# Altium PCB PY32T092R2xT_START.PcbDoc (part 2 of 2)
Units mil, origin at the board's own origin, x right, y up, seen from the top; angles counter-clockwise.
Board outline 1771.65 x 3866.06 mil, 2 copper layers (Top Layer, Bottom Layer), stack 21 mil thick; 144 components, 162 nets, 571 pads, 266 vias.
Unrouted connection lines stored in the file: 5.
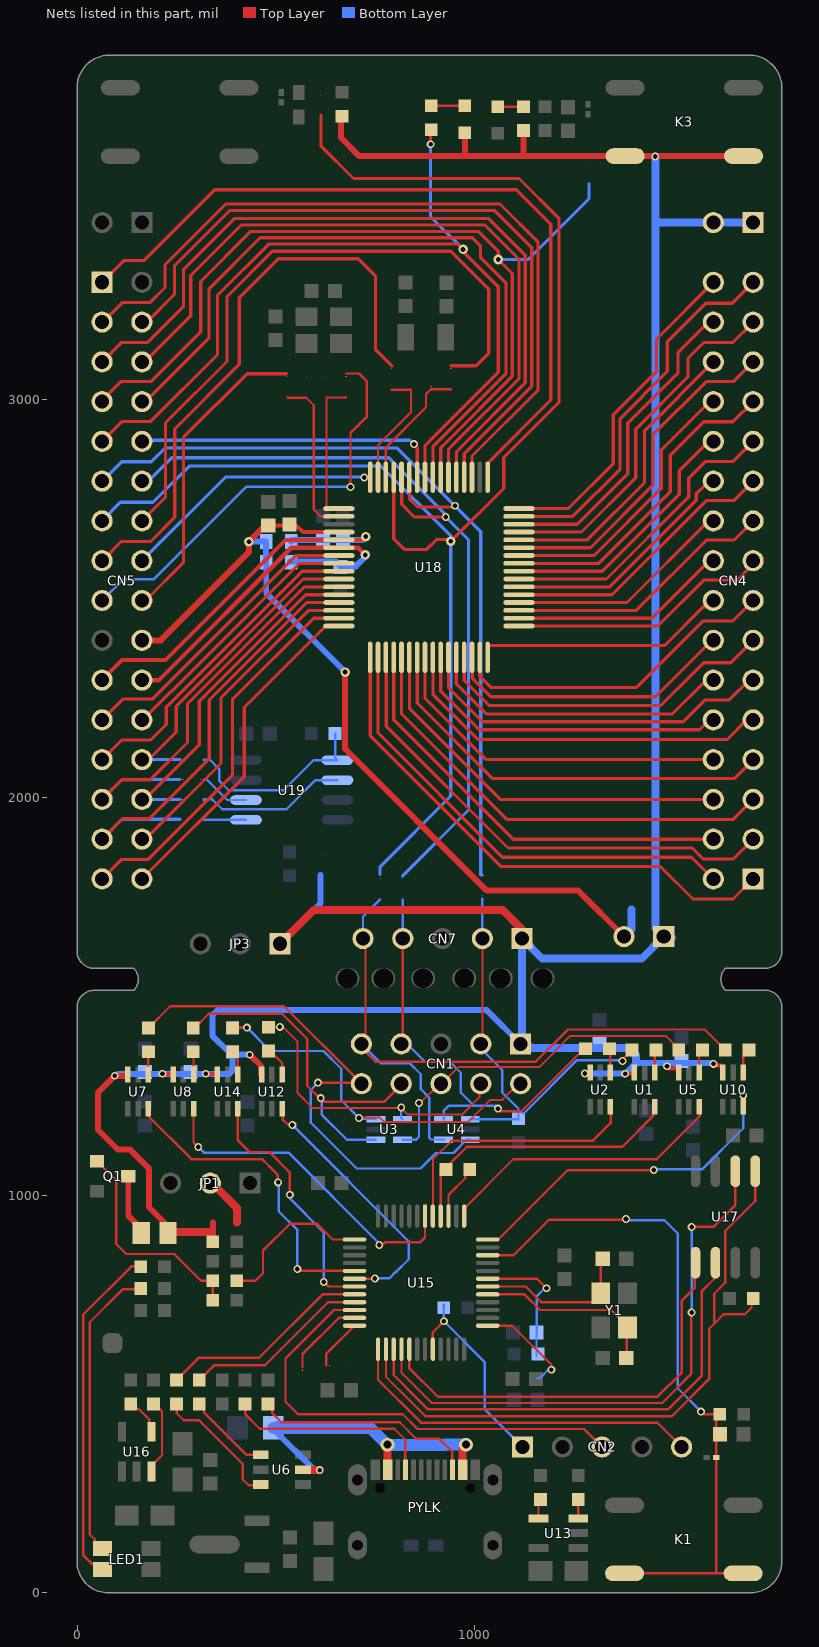
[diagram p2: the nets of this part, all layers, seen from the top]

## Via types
v1: diameter 19.68, hole 11.81, Top Layer to Bottom Layer, tented both sides, 132 vias
v2: diameter 19.68, hole 11.81, Top Layer to Bottom Layer, 72 vias
v3: diameter 24, hole 12, Top Layer to Bottom Layer, tented both sides, 50 vias
v4: diameter 35, hole 20, Top Layer to Bottom Layer, tented both sides, 8 vias
v5: diameter 30, hole 15, Top Layer to Bottom Layer, tented both sides, 2 vias
v6: diameter 40, hole 20, Top Layer to Bottom Layer, tented both sides, 2 vias

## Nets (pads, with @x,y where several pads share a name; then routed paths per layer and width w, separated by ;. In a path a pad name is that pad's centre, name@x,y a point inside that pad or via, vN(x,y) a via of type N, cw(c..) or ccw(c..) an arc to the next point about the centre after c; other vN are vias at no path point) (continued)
NetLED1_3: LED1.3 R6.1 | length 884.3
  Top Layer w6: LED1.3@44.29,58.63 LED1.3@59,43.93 ; LED1.3@64,58.93 49.29,73.63 36.1,73.63 16.02,93.72 16.02,700.45 136.61,821.05 159.08,821.05 R6.1@160.02,820.12
NetLED1_4: LED1.4 R4.1 | length 755.1
  Top Layer w6: LED1.4@56.68,98.62 44.37,110.92 44.37,134.85 32.02,147.21 32.02,680.45 115.41,763.84 158.74,763.84 R4.1@160.02,765.12
NetLED_PA2_2: LED_PA2.2 R53.1 | length 85
  Top Layer w6: R53.1@890.21,3738.35 LED_PA2.2@975.21,3738.35
NetLED_VDD*_1: LED_VDD*.1 R38.1 | length 65
  Top Layer w6: LED_VDD*.1@1057.21,3736.35 R38.1@1122.21,3736.35
NetPYLK_A5: PYLK.A5 R1.2 | length 530.3
  Top Layer w6: R1.2@422.51,475.11 422.51,449.93 459.53,412.91 797.6,412.91 825.35,385.15 825.35,310.66 PYLK.A5@826.01,310.01
NetPYLK_B5: PYLK.B5 R3.1 | length 566
  Top Layer w6: R3.1@480.02,475.12 490.33,464.81 490.33,452.45 513.87,428.91 811.12,428.91 852.68,387.36 911.56,387.36 943.19,355.73 943.19,310.94 PYLK.B5@944.12,310.01
NetQ1_1: Q1.1 R19.1 R20.2 | length 559
  Top Layer w6: Q1.1@50.02,1084.92 51.98,1084.92 63.73,1073.17 63.73,1071.35 98.48,1036.6 98.48,877.45 123.87,852.06 244.46,852.06 311.62,784.9 R19.1@341.54,784.9 ; R20.2@341.53,736 R19.1@341.53,784.89
NetQ1_3: Q1.3 R15.1 | length 166.5
  Top Layer w6: Q1.3@125.51,1044.27 Q1.3@128.76,1047.52 ; R15.1@161.55,905.12 R15.1@161.55,911.02
  Top Layer w15: Q1.3@128.76,1047.52 128.76,948.4 161.55,915.6 R15.1@161.55,905.12
NetR2_1: R2.1 U1.4 | length 57.9
  Top Layer w6: U1.4@1452.24,1308.42 1452.24,1362.13 R2.1@1455.22,1365.12
NetR7_1: R7.1 U2.4 | length 57.8
  Top Layer w6: R7.1@1338.08,1365.12 1340.81,1362.38 U2.4@1340.81,1308.42
NetR10_1: R10.1 U5.4 | length 60.3
  Top Layer w6: U5.4@1563.67,1308.42 1563.67,1356.42 R10.1@1572.37,1365.12
NetR11_1: R11.1 U6.3 | length 332.9
  Top Layer w6: R11.1@250.02,475.12 250.79,474.34 250.79,451.8 268.43,434.16 306.81,434.16 416.26,324.72 416.26,285.99 431.64,270.6 459.75,270.6 U6.3@461.55,272.4
NetR12_1: R12.1 U6.1 | length 227.7
  Top Layer w6: R12.1@308.77,480.12 319.16,469.72 319.16,453.79 426.01,346.94 U6.1@471.99,346.94
NetR13_1: R13.1 U7.4 | length 59
  Top Layer w6: R13.1@173.56,1360.12 179.15,1354.52 U7.4@179.15,1303.42
NetR14_1: R14.1 U8.4 | length 60.8
  Top Layer w6: R14.1@280.96,1360.13 R14.1@290.84,1350.25 ; U8.4@292.87,1303.42 R14.1@292.87,1350.24
NetR18_1: R18.1 U10.4 | length 62.7
  Top Layer w6: U10.4@1675.1,1308.42 1675.1,1350.71 R18.1@1689.51,1365.12
NetR22_1: R22.1 U12.4 | length 75.3
  Top Layer w6: R22.1@481.65,1362.23 485.64,1362.23 515.73,1332.14 U12.4@515.73,1303.42
NetR24_2: R24.2 U13.4 | length 49.6
  Top Layer w6: U13.4@1160.02,187.62 1160.02,230.12 R24.2@1165.02,235.12
NetR25_2: R25.2 U13.3 | length 47.5
  Top Layer w6: U13.3@1260.02,187.62 R25.2@1260.02,235.12
NetR26_1: R26.1 U14.4 | length 62.8
  Top Layer w6: R26.1@391.22,1360.82 404.3,1347.73 U14.4@404.3,1303.42
NetR27_2: R27.2 U15.1 | length 256.3
  Top Layer w6: U15.1@1032.34,671.85 1094.2,671.85 1192.47,573.57 v2(1192.47,561)
  Bottom Layer w6: 1158.36,539.95 1163.62,539.95 1184.67,561 v2(1192.47,561)
NetR29_2: R29.2 U16.4 | length 96.1
  Top Layer w6: R29.2@135.02,475.12 147.02,463.12 154.46,463.12 181.52,436.06 181.52,411.12 U16.4@187.52,405.12
NetR30_2: R30.2 U16.3 | length 188.5
  Top Layer w6: U16.3@187.52,305.12 187.52,320.12 213.57,346.17 213.57,455.79 207.02,462.35 207.02,463.12 R30.2@195.02,475.12
NetR31_1: R31.1 U15.36 | length 129.6
  Top Layer w6: 626.23,571.86 626.23,600.38 U15.36@697.7,671.85
NetR33_1: R33.1 U15.35 | length 201.4
  Top Layer w6: 566.98,567.51 566.98,600.5 658.02,691.54 U15.35@697.7,691.54
NetR44_1: R44.1 R46.1 U19.1 | length 486
  Bottom Layer w6: 318.06,2094.88 333.56,2094.88 357.32,2071.12 357.32,2042.15 381.47,2018.01 519.43,2018.01 594.74,2093.32 U19.1@654.57,2093.32 648.75,2099.14 R44.1@648.75,2160.34
NetR47_1: R47.1 U19.2 | length 376.2
  Bottom Layer w6: 318.06,1994.88 319.93,1993.01 ; 321.81,1994.88 340.06,1994.88 365.01,1969.93 526.44,1969.93 599.82,2043.32 U19.2@654.57,2043.32
NetR48_2: R48.2 U19.6 | length 127.9
  Bottom Layer w6: 318.06,2044.88 326.03,2044.88 377.6,1993.32 U19.6@424.57,1993.32
NetR49_2: R49.2 U19.5 | length 107.2
  Bottom Layer w6: 318.06,1944.88 319.62,1943.32 U19.5@424.57,1943.32
OSC_32INa: R42.1 R59.2 U18.46 | length 318.7
  Top Layer w6: U18.46@776.4,2804.8 776.4,2860.09 776.4,2879.71 877.4,2980.71 877.4,3013.66 889.68,3025.94 939.19,3025.94 940.02,3025.12
OSC_32OUTa: R41.1 R61.2 U18.47 | length 303.4
  Top Layer w6: U18.47@756.72,2804.8 756.72,2885.01 839.69,2967.98 839.69,3025.12 791.02,3025.12
OSC_INa: R40.1 R55.2 U18.49 | length 358
  Top Layer w6: U18.49@658.3,2726.07 629.9,2726.07 627.22,2728.75 627.22,2860.5 627.28,2860.57 627.28,3005.31 675.57,3005.31 675.97,3005.72 676.23,3005.46
OSC_OUTa: R39.1 R57.2 U18.50 | length 406.5
  Top Layer w6: 529.27,3005.72 530.5,3004.49 576.23,3004.49 595.02,2985.7 595.02,2723.69 611.59,2707.11 657.57,2707.11 U18.50@658.3,2706.38
PA0: CN5.7 R58.2 U18.39 | length 2256.3
  Top Layer w8: CN5.7@63.06,2994.88 63.06,2998.16 110.02,3045.12 185.47,3045.12 311.06,3170.71 311.06,3296.88 437.06,3422.88 1009.06,3422.88 1058.95,3372.99 v3(1058.95,3352.13) 1094.06,3317.01 1094.06,3058.47 930.29,2894.7 930.29,2894.61 914.2,2878.53 U18.39@914.2,2804.8
  Bottom Layer w8: v3(1058.95,3352.13) 1134.03,3352.13 1287.02,3505.12 1287.02,3543.12
PA1: CN5.8 U18.40 | length 1786.7
  Top Layer w8: CN5.8@163.06,2994.88 171.24,2994.88 332.06,3155.7 332.06,3278.88 460.06,3406.88 994.06,3406.88 1014.1,3386.84 1014.1,3357.84 1078.06,3293.88 1078.06,3065.1 914.29,2901.33 914.29,2901.24 894.51,2881.46 U18.40@894.51,2804.8
PA2: CN5.9 R53.2 U18.41 | length 2234.7
  Top Layer w8: CN5.9@63.06,2894.88 113.29,2945.12 185.18,2945.12 353.06,3112.99 353.06,3261.88 482.06,3390.88 957.2,3390.88 v3(970.59,3377.49) 970.59,3371.99 1059.06,3283.52 1059.06,3068.73 898.29,2907.96 898.29,2907.87 874.83,2884.41 U18.41@874.83,2804.8 ; v1(888.98,3641.73) 888.98,3677.11 R53.2@895.98,3684.12
  Bottom Layer w8: v1(888.98,3641.73) 888.98,3459.1 v3(970.59,3377.49)
PA3: CN5.10 U18.42 | length 775.8
  Top Layer w8: v1(847.05,2887.91) 855.14,2879.82 U18.42@855.14,2804.8
  Bottom Layer w8: CN5.10@163.06,2894.88 166.06,2897.88 837.08,2897.88 v1(847.05,2887.91)
PA4: CN5.11 R51.2 U18.43 | length 2118.7
  Top Layer w8: U18.43@835.46,2804.8 835.46,2750.48 856.06,2729.88 947.06,2729.88 v1(950.06,2732.88)
  Bottom Layer w8: CN5.11@63.06,2794.88 112.06,2843.88 187.06,2843.88 221.06,2877.88 805.06,2877.88 v1(950.06,2732.88) 1014.94,2668 1014.94,1805.18 1018.95,1805.18
PA5: CN5.12 R52.2 U18.44 | length 2039.7
  Top Layer w8: U18.44@815.77,2804.8 816.5,2804.07 816.5,2736.44 848.06,2704.88 v1(927.06,2704.88)
  Bottom Layer w8: CN5.12@163.06,2794.88 179.06,2794.88 238.06,2853.88 784.06,2853.88 927.06,2710.88 v1(927.06,2704.88) 984.06,2647.88 984.06,1968.22 818.95,1803.12
PA6: CN5.14 R42.2 | length 1665.8
  Top Layer w8: CN5.14@163.06,2694.88 222.48,2754.31 222.48,2941.25 377.06,3095.83 377.06,3258.88 491.06,3372.88 939.06,3372.88 1035.06,3276.88 1035.06,3116.88 1003.29,3085.12 940.02,3085.12
PA7: CN5.15 R41.2 | length 1490.2
  Top Layer w8: CN5.15@63.06,2594.88 111.29,2643.12 184.95,2643.12 245.61,2703.77 245.61,2926.13 408.06,3088.58 408.06,3255.88 506.06,3353.88 707.06,3353.88 750.06,3310.88 750.06,3126.07 791.02,3085.12
PA8: CN5.16 U18.48 | length 661.6
  Top Layer w8: v1(722.07,2804.24) 722.63,2804.8 U18.48@737.03,2804.8
  Bottom Layer w8: CN5.16@163.06,2594.88 373.29,2805.12 721.19,2805.12 v1(722.07,2804.24)
PA9: CN5.17 R40.2 | length 1085.4
  Top Layer w6: 676.05,3065.63 676.23,3065.63 ; 676.23,3065.46 709.23,3065.46 727.92,3046.76 727.92,2956.34 687.5,2915.91 v1(687.5,2780.37)
  Bottom Layer w6: CN5.17@63.06,2494.88 116.06,2547.88 192.62,2547.88 425.11,2780.37 v1(687.5,2780.37)
PA10: CN5.18 R39.2 | length 784.4
  Top Layer w8: CN5.18@163.06,2494.88 172.06,2494.88 267.39,2590.21 267.39,2904.82 427.69,3065.12 527.02,3065.12
PA13: CN5.23 U18.55 | length 766.3
  Top Layer w8: CN5.23@63.06,2194.88 115.29,2247.12 189.52,2247.12 282.02,2339.61 549.64,2607.23 657.57,2607.23 U18.55@658.3,2607.96
PA14: CN5.24 U18.56 | length 659.3
  Top Layer w8: CN5.24@163.06,2194.88 164.44,2193.5 311.02,2340.08 559.2,2588.27 U18.56@658.3,2588.27
PA15: CN5.25 U18.57 | length 817
  Top Layer w8: CN5.25@63.06,2094.88 112.29,2144.12 185.04,2144.12 224.14,2183.21 224.14,2226.74 565.98,2568.59 U18.57@658.3,2568.59
PB0: CN5.26 R46.2 U18.58 | length 816.3
  Top Layer w8: CN5.26@163.06,2094.88 179.83,2094.88 249.26,2164.31 249.26,2229.24 568.92,2548.9 U18.58@658.3,2548.9
  Bottom Layer w8: CN5.26@163.06,2094.88 258.06,2094.88
PB1: CN5.27 R48.1 U18.59 | length 1089.1
  Top Layer w8: CN5.27@63.06,1994.88 112.29,2044.12 183.82,2044.12 277.66,2137.95 277.66,2235.01 571.86,2529.22 U18.59@658.3,2529.22
  Bottom Layer w8: CN5.27@63.06,1994.88 113.06,2044.88 258.06,2044.88
PB2: CN5.28 R47.2 U18.60 | length 867.7
  Top Layer w8: CN5.28@163.06,1994.88 169.96,1994.88 307.36,2132.28 307.36,2242.09 574.57,2509.29 658.06,2509.29 U18.60@658.3,2509.53
  Bottom Layer w8: CN5.28@163.06,1994.88 258.06,1994.88
PB3: CN5.29 R49.1 U18.61 | length 1143.9
  Top Layer w8: CN5.29@63.06,1894.88 114.29,1946.12 181.72,1946.12 332.56,2096.95 332.56,2244.66 577.75,2489.85 U18.61@658.3,2489.85
  Bottom Layer w8: CN5.29@63.06,1894.88 113.06,1944.88 258.06,1944.88
PB4: CN5.30 U18.62 | length 830.1
  Top Layer w8: CN5.30@163.06,1894.88 171.62,1894.88 361.96,2085.22 361.96,2250.06 582.06,2470.16 U18.62@658.3,2470.16
PB5: CN5.31 U18.63 | length 978.2
  Top Layer w8: CN5.31@63.06,1794.88 112.29,1844.12 178.76,1844.12 390.56,2055.91 390.56,2246.08 594.95,2450.48 U18.63@658.3,2450.48
PB6: CN5.32 U18.64 | length 860.5
  Top Layer w8: CN5.32@163.06,1794.88 420.26,2052.08 420.26,2225.9 625.15,2430.79 U18.64@658.3,2430.79
PB7: CN4.1 U18.1 | length 1350.5
  Top Layer w8: U18.1@737.03,2352.06 737.03,2155.29 1066.33,1825.98 1466.82,1825.98 1548.43,1744.38 1649.11,1744.38 CN4.1@1699.61,1794.88
PB8: CN4.2 U18.2 | length 1184.9
  Top Layer w8: U18.2@756.72,2352.06 756.72,2162.14 1069.25,1849.61 1544.88,1849.61 CN4.2@1599.61,1794.88
PB9: CN4.3 U18.3 | length 1254.7
  Top Layer w8: U18.3@776.4,2352.06 777.51,2350.95 777.51,2178.77 1083.45,1872.83 1546.69,1872.83 1574.41,1845.12 1649.84,1845.12 CN4.3@1699.61,1894.88
PB10: CN4.4 U18.4 | length 1084.9
  Top Layer w8: U18.4@796.09,2352.06 796.09,2195.01 1096.21,1894.88 CN4.4@1599.61,1894.88
PB11: CN4.5 U18.5 | length 1157
  Top Layer w8: U18.5@815.77,2352.06 815.77,2210.18 1081.83,1944.12 1648.84,1944.12 CN4.5@1699.61,1994.88
PB12: CN4.6 U18.6 | length 987.2
  Top Layer w8: U18.6@835.46,2352.06 835.46,2223.78 1064.35,1994.88 CN4.6@1599.61,1994.88
PB13: CN4.7 U18.7 | length 1057.9
  Top Layer w8: U18.7@855.14,2352.06 855.14,2237.12 1045.15,2047.12 1651.84,2047.12 CN4.7@1699.61,2094.88
PB14: CN4.8 U18.8 | length 891.6
  Top Layer w8: U18.8@874.83,2352.06 874.83,2249.17 1029.12,2094.88 CN4.8@1599.61,2094.88
PB15: CN4.9 U18.9 | length 965.9
  Top Layer w8: U18.9@894.51,2352.06 894.51,2259.02 1008.41,2145.12 1257.29,2145.12 1633.94,2145.12 1683.71,2194.88 CN4.9@1699.61,2194.88
PC0: CN4.10 U18.10 | length 820.8
  Top Layer w8: U18.10@914.2,2352.06 914.2,2267.18 1011.36,2170.02 1242.06,2170.02 1564.92,2170.02 1589.78,2194.88 CN4.10@1599.61,2194.88
PC1: CN4.11 U18.11 | length 921.3
  Top Layer w8: U18.11@933.88,2352.06 933.88,2275.35 1019.34,2189.88 1524.06,2189.88 1579.29,2245.12 1639.66,2245.12 1689.43,2294.88 CN4.11@1699.61,2294.88
PC2: CN4.12 U18.12 | length 779.2
  Top Layer w8: U18.12@953.57,2352.06 953.57,2285.32 1029.01,2209.88 1497.06,2209.88 1582.06,2294.88 CN4.12@1599.61,2294.88
PC3: CN4.13 U18.13 | length 878.6
  Top Layer w8: U18.13@973.25,2352.06 973.25,2293.75 1036.11,2230.88 1467.87,2230.88 1550.11,2313.12 1575.37,2338.38 1643.1,2338.38 CN4.13@1699.61,2394.88
PC4: CN4.14 U18.14 | length 736.9
  Top Layer w8: U18.14@992.94,2352.06 993.67,2351.33 993.67,2299.62 1040.41,2252.88 1454.26,2252.88 1596.26,2394.88 CN4.14@1599.61,2394.88
PC5: CN4.15 U18.15 | length 837.2
  Top Layer w8: U18.15@1012.62,2352.06 1012.62,2304.38 1041.11,2275.88 1405.4,2275.88 1489.63,2360.12 1572.63,2443.12 1647.84,2443.12 CN4.15@1699.61,2494.88
PC6: CN4.16 U18.16 | length 641.7
  Top Layer w8: U18.16@1032.31,2352.06 1032.31,2378.13 1036.06,2381.88 1477.06,2381.88 1574.41,2479.23 1583.96,2479.23 CN4.16@1599.61,2494.88
PC7: CN4.17 U18.17 | length 661.3
  Top Layer w8: U18.17@1111.04,2430.79 1459.97,2430.79 1575.29,2546.12 1659.02,2546.12 1699.61,2586.71 CN4.17@1699.61,2594.88
PC8: CN4.18 U18.18 | length 548.4
  Top Layer w8: U18.18@1111.04,2450.48 1444.66,2450.48 1589.06,2594.88 CN4.18@1599.61,2594.88
PC9: CN4.19 U18.19 | length 681.7
  Top Layer w8: U18.19@1111.04,2470.16 1405.93,2470.16 1582.89,2647.12 1651.84,2647.12 CN4.19@1699.61,2694.88
PC10: CN4.20 U18.20 | length 573.5
  Top Layer w8: U18.20@1111.04,2489.85 1382.62,2489.85 1586.98,2694.21 1598.93,2694.21 CN4.20@1599.61,2694.88
PC11: CN4.21 U18.21 | length 706.8
  Top Layer w8: U18.21@1111.04,2509.53 1344.9,2509.53 1581.48,2746.12 1650.84,2746.12 CN4.21@1699.61,2794.88
PC12: CN4.22 U18.22 | length 608.2
  Top Layer w8: U18.22@1111.04,2529.22 1339.4,2529.22 1556.86,2746.68 1556.86,2763.08 1583.99,2790.21 1594.93,2790.21 CN4.22@1599.61,2794.88
PC13: CN4.23 U18.23 | length 759.3
  Top Layer w8: U18.23@1111.04,2548.9 1331.08,2548.9 1537.76,2755.58 1537.76,2802.44 1579.43,2844.12 1648.84,2844.12 CN4.23@1699.61,2894.88
PC14: CN4.24 U18.24 | length 658.5
  Top Layer w8: U18.24@1111.04,2568.59 1320.77,2568.59 1514.16,2761.98 1514.16,2821.32 1587.72,2894.88 CN4.24@1599.61,2894.88
PC15: CN4.25 U18.25 | length 810.6
  Top Layer w8: U18.25@1111.04,2588.27 1311.45,2588.27 1491.46,2768.28 1491.46,2859.87 1575.71,2944.12 1648.84,2944.12 CN4.25@1699.61,2994.88
PD0: CN4.26 U18.26 | length 705.4
  Top Layer w8: U18.26@1111.04,2607.96 1300.14,2607.96 1468.79,2776.61 1468.79,2873.15 1588.84,2993.21 1597.93,2993.21 CN4.26@1599.61,2994.88
PD1: CN4.27 U18.27 | length 856.4
  Top Layer w8: U18.27@1111.04,2627.64 1290.82,2627.64 1447.62,2784.44 1447.62,2911.32 1581.41,3045.12 1649.84,3045.12 CN4.27@1699.61,3094.88
PD2: CN4.28 U18.28 | length 750.4
  Top Layer w8: U18.28@1111.04,2647.33 1282.51,2647.33 1426.83,2791.66 1426.83,2922.11 CN4.28@1599.61,3094.88
PD3: CN4.29 U18.29 | length 906.4
  Top Layer w8: U18.29@1111.04,2667.01 1268.19,2667.01 1404.46,2803.29 1404.46,2925.56 1536.02,3057.12 1536.02,3104.12 1575.02,3143.12 1647.84,3143.12 CN4.29@1699.61,3194.88
PD4: CN4.30 U18.30 | length 804.1
  Top Layer w8: U18.30@1111.04,2686.7 1257.88,2686.7 1384.31,2813.13 1384.31,2940.41 1511.02,3067.12 1511.02,3119.12 1586.78,3194.88 CN4.30@1599.61,3194.88
PD5: CN4.31 U18.31 | length 950.2
  Top Layer w8: U18.31@1111.04,2706.38 1246.56,2706.38 1365.33,2825.16 1365.33,2952.06 1484.02,3070.74 1484.02,3145.12 1581.02,3242.12 1646.84,3242.12 CN4.31@1699.61,3294.88
PD6: CN4.32 U18.32 | length 843.9
  Top Layer w8: U18.32@1111.04,2726.07 1235.25,2726.07 1347.99,2838.82 1347.99,2962.09 1457.02,3071.12 1457.02,3152.29 CN4.32@1599.61,3294.88
PD7: CN5.1 U18.33 | length 1962.1
  Top Layer w8: CN5.1@63.06,3294.88 117.56,3349.38 167.56,3349.38 345.8,3527.62 1104.32,3527.62 1191.02,3440.92 1191.02,2998.84 1032.31,2840.13 U18.33@1032.31,2804.8
PD9: CN5.3 U18.35 | length 1951.9
  Top Layer w8: CN5.3@63.06,3194.88 64.39,3194.88 113.33,3243.83 183,3243.83 221.06,3281.88 221.06,3338.96 373.72,3491.62 1063.32,3491.62 1159.02,3395.93 1159.02,3024.18 992.94,2858.1 U18.35@992.94,2804.8
PD10: CN5.4 U18.36 | length 1824.3
  Top Layer w8: CN5.4@163.06,3194.88 175.06,3194.88 245.06,3264.88 245.06,3336.2 384.48,3475.62 1049.32,3475.62 1143.02,3381.93 1143.02,3033.92 973.25,2864.16 U18.36@973.25,2804.8
PD11: CN5.5 U18.37 | length 1935.6
  Top Layer w8: CN5.5@63.06,3094.88 111.29,3143.12 176.29,3143.12 268.06,3234.88 268.06,3327.88 395.06,3454.88 1035.06,3454.88 1127.02,3362.92 1127.02,3042.17 954.3,2869.45 954.3,2805.53 U18.37@953.57,2804.8
PD12: CN5.6 U18.38 | length 1806.9
  Top Layer w8: CN5.6@163.06,3094.88 170.34,3094.88 286.06,3210.6 286.06,3311.88 413.06,3438.88 1025.06,3438.88 1111.02,3352.92 1111.02,3052.8 946.29,2888.07 946.29,2887.99 933.88,2875.58 U18.38@933.88,2804.8
PD13: CN5.13 R50.2 R54.2 U18.45 | length 3928.4
  Top Layer w8: 613.06,3714.88 613.06,3637.78 694.96,3555.88 1111.06,3555.88 1212.06,3454.88 1212.06,2993.88 1072.56,2854.38 1072.56,2776.54 v3(939.73,2643.72) 935.17,2648.28 904.03,2648.28 879.18,2623.43 823.01,2623.43 796.09,2650.35 U18.45@796.09,2804.8
  Bottom Layer w8: CN5.13@63.06,2694.88 63.06,2695.88 109.06,2741.88 191.06,2741.88 282.06,2832.88 764.06,2832.88 939.33,2657.61 939.33,2644.12 v3(939.73,2643.72) 939.73,2003.56 762.02,1825.84 762.02,1806.87
PYLK_BOOT0: CN2.1 R28.1 U15.44 | length 523
  Top Layer w6: U15.44@894.55,612.8 894.55,655.18 v1(922.23,682.87)
  Bottom Layer w6: R28.1@923.28,724.52 920.5,721.75 922.23,720.02 v1(922.23,682.87) 1024.71,580.38 1024.71,462.23 CN2.1@1120.06,366.88
PYLK_KEY: C6.2 K1.1 K1.2 R16.1 U11.1 U15.10 | length 1775.4
  Top Layer w6: U15.10@1032.34,849.02 1097.15,849.02 1186.46,938.32 1378.22,938.32 v1(1380.02,940.12) ; K1.2@1376.56,49.12 K1.1@1674.56,49.12 K1.1@1653.52,49.12 ; v1(1568.57,455.86) 1575.56,448.88 R16.1@1616.06,448.88 1607.32,440.14 U11.1@1607.32,340.12 1607.32,49.12
  Bottom Layer w6: v1(1380.02,940.12) 1383.08,937.05 1392.64,937.05 1392.7,936.99 1476.66,936.99 1510.02,903.63 1510.02,514.42 v1(1568.57,455.86)
PYLK_NRST: C24.2 R36.1 U15.7 | length 341.9
  Top Layer w6: U15.7@1032.34,789.96 1156.38,789.96 v1(1180.42,765.91)
  Bottom Layer w6: R36.1@1155.14,595.12 1155.14,654.11 1156.14,655.12 1156.14,746.12 1175.94,765.91 v1(1180.42,765.91)
PYLK_OSCIN: C19.2 U15.5 Y1.3 | length 465.6
  Top Layer w6: U15.5@1032.34,750.59 1125.07,750.59 1164.44,711.22 1343.13,711.22 1383.6,670.74 Y1.3@1383.6,666.81 1382.14,665.34 C19.2@1382.14,590.12
PYLK_OSCOUT: C25.2 U15.6 Y1.1 | length 399.8
  Top Layer w6: U15.6@1032.34,770.28 1128,770.28 1167.37,730.9 1297.05,730.9 1316.67,750.53 Y1.1@1316.67,753.43 1316.67,836.65 C25.2@1320.14,840.12
PYLK_SPI_CS: R35.1 U15.38 U17.1 | length 1667.6
  Top Layer w5: U15.38@776.44,612.8 776.44,543.73 837.68,482.49
  Top Layer w6: 837.68,482.49 875.96,444.21 1495.52,444.21 1588.9,537.58 1588.9,664 1601.78,676.88 ; R35.1@1700.02,740.12 1695.64,735.74 1695.64,716.8 1679.37,700.54 1625.44,700.54 1601.78,676.88 ; U17.1@1705.02,1060.11 1705.02,985.12 1629.71,909.81 1629.71,780.13 1601.78,752.2 1601.78,676.88
PYLK_SPI_MISO: U15.40 U17.2 | length 1437.2
  Top Layer w6: U15.40@815.81,612.8 815.81,553.42 891.81,477.41 1471.02,477.41 1543.92,550.31 1543.92,704.02 v1(1545.02,705.12) ; v1(1545.02,920.12) 1600.02,920.12 1655.02,975.12 U17.2@1655.02,1060.11
  Bottom Layer w6: v1(1545.02,705.12) v1(1545.02,920.12)
PYLK_SPI_MOSI: U15.41 U17.5 | length 1077.9
  Top Layer w6: U15.41@835.49,612.8 835.49,564.6 906.68,493.41 1459.43,493.41 1520.55,554.53 1520.55,735.2 1553.15,767.8 1553.15,828.25 U17.5@1555.02,830.11
PYLK_SPI_SCK: U15.39 U17.6 | length 1208.9
  Top Layer w6: U15.39@796.12,612.8 796.12,547.48 856.34,487.26 882.18,461.41 1486.09,461.41 1570.23,545.55 1570.23,758.18 1601.95,789.9 1601.95,827.05 U17.6@1605.02,830.11
SWD_SCK: CN2.5 U15.37 | length 910.2
  Top Layer w6: U15.37@756.75,612.8 756.75,535.87 864.5,428.12 1458.83,428.12 CN2.5@1520.06,366.88
SWD_SDA: CN2.3 U15.34 | length 1175.7
  Top Layer w6: U15.34@697.7,711.22 646.13,711.22 524.07,589.16 524.07,480.83 555.58,449.32 818.77,449.32 855.97,412.12 1274.83,412.12 CN2.3@1320.06,366.88
T_RESET: CN1.9 CN7.5 R18.2 R54.1 U4.4 | length 1773.4
  Top Layer w6: CN1.9@715.02,1380.12 725.2,1390.3 725.2,1638.87 CN7.5@718.95,1645.12 ; CN1.9@722.79,1362.89 750.21,1335.48 1152.92,1335.48 1234,1416.55 1578.07,1416.55 R18.2@1629.51,1365.12
  Bottom Layer w6: CN1.9@726.02,1391.12 CN1.9@715.02,1380.12 763.24,1331.89 836.03,1331.89 864.12,1303.81 864.12,1266.54 885.17,1245.49 885.17,1144.43 889.63,1139.97 921.11,1139.97 U4.4@921.55,1139.52 ; CN7.5@726.02,1638.05 CN7.5@718.95,1645.12 718.95,1700.05 762.02,1743.12
T_RESETa: U10.3 U15.12 | length 870.1
  Top Layer w6: U15.12@1032.34,888.39 1058.8,888.39 1233.49,1063.07 1321.55,1063.07 v1(1449.93,1063.07) ; v1(1674.83,1250.82) 1675.1,1250.55 U10.3@1675.1,1221.81
  Bottom Layer w6: v1(1449.93,1063.07) 1451.67,1064.81 1571.42,1064.81 1674.83,1168.23 v1(1674.83,1250.82)
T_RTCK_DTRa: U5.3 U15.13 | length 731.2
  Top Layer w6: U15.13@973.29,947.44 973.29,966.69 1096.72,1090.12 1457.01,1090.12 1565.2,1198.31 1565.2,1220.28 U5.3@1563.67,1221.81
T_RTCK_VCP_DTR: CN1.6 R10.2 U3.5 | length 868.3
  Top Layer w5: v1(859.83,1231.78) 863.26,1231.78 911.59,1280.12 CN1.6@915.02,1280.12 916.65,1280.12 958.51,1321.98 1161.74,1321.98 1240.32,1400.55 1480,1400.55 1500.37,1380.18 1500.37,1377.12 R10.2@1512.37,1365.12
  Bottom Layer w6: U3.5@818.48,1139.52 852.53,1139.52 859.83,1146.82 v1(859.83,1231.78)
T_TCK_SWCLK: CN1.7 CN7.4 R7.2 R52.1 U4.5 | length 1101.8
  Top Layer w6: CN1.7@815.02,1380.12 818.95,1384.05 CN7.4@818.95,1645.12 ; CN7.4@820.02,1645.12 CN7.4@821.36,1643.77 ; v1(1058.52,1217.44) 1065.15,1210.8 1116.98,1210.8 1271.29,1365.12 R7.2@1278.08,1365.12
  Bottom Layer w6: CN1.7@815.02,1380.12 820.02,1385.12 CN1.7@820.02,1387.62 ; 818.95,1743.12 CN7.4@818.95,1645.12 CN7.4@820.02,1644.05 ; CN1.7@822.52,1387.62 875.49,1334.64 937.66,1334.64 964.62,1307.69 964.62,1257.66 997.16,1225.12 ; U4.5@921.55,1190.71 921.55,1211.65 935.02,1225.12 997.16,1225.12 ; v1(1058.52,1217.44) 1050.84,1225.12 997.16,1225.12
T_TCK_SWCLKa: U2.3 U15.17 | length 668.1
  Top Layer w5: U15.17@894.55,947.44 894.55,1089.87 941.79,1137.12
  Top Layer w6: 941.79,1137.12 1047.64,1137.12 1297.44,1137.12 1341.42,1181.1 1341.42,1221.2 U2.3@1340.81,1221.81
T_TDI_VCP_TX: CN1.4 R22.2 U3.4 | length 783.1
  Top Layer w5: R22.2@481.65,1422.23 517.92,1422.23 554.55,1385.6 554.55,1256.74 592.31,1218.98 v1@815.02,1218.98 ; R22.2@481.65,1425.23 R22.2@483.15,1423.73 ; v1@815.04,1218.98 831.79,1202.22 967.78,1202.22 1011.57,1246.02 1011.57,1276.67 CN1.4@1015.02,1280.12
  Bottom Layer w5: v1@815.07,1220.06 815.07,1194.11 U3.4@818.48,1190.71
  other v1: 815.02,1220.12
  other v2: 509.98,1423.1
T_TDI_VCP_TXa: U12.3 U15.30 | length 672.4
  Top Layer w6: U12.3@515.73,1216.81 516.95,1215.59 516.95,1190.48 529.25,1178.18 539.58,1178.18 v1(541.33,1176.43) ; U15.30@697.7,789.96 748.03,789.96 v1(748.77,790.69)
  Bottom Layer w6: v1(541.33,1176.43) 834.11,883.64 834.11,839.03 801.58,806.5 800.73,806.5 784.92,790.69 v1(748.77,790.69)
T_TDO_SWO: CN1.10 R13.2 U4.3 | length 1333.3
  Top Layer w6: R13.2@179.67,1420.2 234.49,1475.02 520.12,1475.02 CN1.10@708.53,1286.6 ; v1(605.88,1282.86) 606.55,1282.19 704.12,1282.19 CN1.10@708.53,1286.6 ; CN1.10@715.02,1280.12 CN1.10@708.53,1286.6
  Bottom Layer w6: v1(605.88,1282.86) 587.85,1264.83 587.85,1182.2 703.08,1066.97 863.3,1066.97 902.43,1106.1 946.47,1106.1 979.89,1139.52 U4.3@988.48,1139.52 U4.3@986.17,1137.21
T_TDO_SWOa: U7.3 U15.29 | length 807.7
  Top Layer w6: U7.3@179.15,1216.81 179.15,1198.98 287.47,1090.66 465.1,1090.66 471.64,1084.12 472.03,1084.12 489.02,1067.13 489.02,1066.74 504.95,1050.81 504.95,1032.81 v1(505.64,1032.12) ; v1(553.89,814.45) 558.7,809.65 641.56,809.65 U15.29@697.7,809.65
  Bottom Layer w6: v1(505.64,1032.12) 506.96,1030.79 506.96,959.05 553.89,912.11 v1(553.89,814.45)
T_TMS_SWDIO: CN1.3 CN7.2 R2.2 R5.2 R51.1 U4.1 | length 1050.7
  Top Layer w6: CN1.3@1015.02,1380.12 1019.32,1384.42 CN7.2@1019.32,1644.75 ; CN1.3@1019.39,1366.3 CN1.3@1025.57,1360.12 ; v1@1371.64,1335.29 1371.64,1340.59 1383.22,1352.17 1383.22,1353.12 R2.2@1395.22,1365.12
  Bottom Layer w6: U4.1@988.78,1190.4 1108.04,1190.4 R5.2@1109.84,1192.2 1109.84,1217.04 1068.88,1258 1068.88,1314.53 CN1.3@1023.6,1359.81 ; CN1.3@1015.02,1380.12 CN1.3@1019.02,1384.12 ; 1018.95,1745.18 CN7.2@1018.95,1646.18 ; CN7.2@1019.02,1645.05 CN7.2@1018.95,1645.12 CN7.2@1018.95,1646.18 ; CN7.2@1019.48,1645.65 CN7.2@1018.95,1646.18 ; R5.2@1123.4,1205.76 1257,1339.37 1369.26,1339.37 v1(1371.45,1337.19)
T_TMS_SWDIOa: R32.1 U1.3 U15.16 | length 723.8
  Top Layer w6: U15.16@914.23,947.44 R32.1@914.23,1067.48 ; R32.1@927.48,1064.48 927.48,1069.11 980.14,1121.77 1036.71,1121.77 1371.24,1121.77 1448.35,1198.88 1448.35,1217.92 U1.3@1452.24,1221.81
T_TMS_SWDIOa_OUT: R32.2 U15.15 | length 143.2
  Top Layer w6: U15.15@933.92,947.44 933.92,1000.76 975.83,1042.68 R32.2@975.83,1073.28
T_TRST_RTSa: U8.3 U15.18 | length 840.3
  Top Layer w6: U8.3@292.87,1216.81 292.87,1132.98 v1(304.83,1121.02) ; v1(759.94,874.47) 763.84,870.56 774.56,881.27 862.41,881.27 874.86,893.72 U15.18@874.86,947.44
  Bottom Layer w6: v1(304.83,1121.02) 318.83,1107.02 531.67,1107.02 759.94,878.75 v1(759.94,874.47)
T_TRST_VCP_RTS: CN1.8 R14.2 U3.1 | length 935
  Top Layer w6: R14.2@292.32,1420.22 295.55,1420.22 331.25,1455.92 515.27,1455.92 578.59,1392.59 578.59,1274.68 609.42,1243.85 v1(612.88,1243.85) 621.62,1235.12 772.68,1235.12 820.02,1282.45 CN1.8@820.02,1290.12
  Bottom Layer w6: v1(612.88,1243.85) 615.02,1241.71 615.02,1202.71 678.2,1139.52 U3.1@751.55,1139.52
T_VCP_RX: CN1.2 R23.1 R26.2 U3.3 | length 1000.9
  Top Layer w5: v1(708.99,1193.85) 710.25,1195.12 761.43,1195.12 772.47,1184.08 983.92,1184.08 1039.32,1239.48 1069.38,1239.48 CN1.2@1120.02,1290.12
  Top Layer w6: R26.2@391.22,1420.82 426.72,1420.82 v2(427.02,1421.12) ; R26.2@391.22,1431.96 R26.2@391.34,1432.08
  Bottom Layer w6: R23.1@391.02,1420.12 392.02,1421.12 v2(427.02,1421.12) 485.73,1362.4 619.28,1362.4 664.06,1317.62 664.06,1238.78 v1(708.99,1193.85) 708.25,1193.12 708.25,1191.88 750.38,1191.88 U3.3@751.55,1190.71
T_VCP_RXa: U14.3 U15.31 | length 636
  Top Layer w6: U14.3@404.3,1216.81 404.3,1137.4 433.29,1108.41 483.55,1108.41 534.42,1057.55 534.42,1001.5 v1(535.02,1000.9) ; v1(620.42,781.87) 632.01,770.28 U15.31@697.7,770.28
  Bottom Layer w6: v1(535.02,1000.9) 535.02,991.54 620.42,906.14 v1(620.42,781.87)
TVDD: C12.2 C13.2 C14.2 C15.2 CN1.1 CN3.1 CN3.2 CN7.1 JP2.1 JP3.1 K3.1 K3.2 LED_PA2.1 R15.2 R17.2 R23.2 R34.2 R37.1 R38.2 R43.2 R70.1 U1.6 U2.6 U5.6 U7.6 U8.6 U10.6 U12.6 U14.6 | length 7940.1
  Top Layer w6: U8.6@241.69,1303.42 U8.6@244.58,1306.31 ; U14.6@353.12,1303.42 U14.6@356.01,1306.31
  Top Layer w10: v1(215.02,1305.12) 240,1305.12 U8.6@241.69,1303.42 ; v2@325.02,1305.12 351.43,1305.12 U14.6@353.12,1303.42 ; v1(1276.58,1305.84) 1279.17,1308.42 U2.6@1289.63,1308.42 ; v2(1377.9,1305.2) 1399.08,1305.2 1399.17,1305.12 1401.06,1307 U1.6@1401.06,1308.42 ; v1(1483.3,1324.17) 1488.63,1318.85 1512.49,1318.85 U5.6@1512.49,1308.42 ; v1@1608.7,1326.21 1618.92,1326.21 1623.92,1321.22 U10.6@1623.92,1308.42
  Top Layer w15: v1(95.02,1300.12) 52.51,1257.61 52.51,1164.89 103.09,1114.32 133.43,1114.32 180.54,1067.21 180.54,970.06 220.53,930.07 220.53,913.06 R15.2@228.48,905.12 R15.2@230.26,906.89 ; v1@95.65,1299.48 U7.6@127.36,1299.48 ; 338.09,906.89 342.1,902.88 ; R17.2@342.1,874.14 342.1,902.88 ; 342.1,931.63 342.1,902.88 ; v2(434.29,1353.16) 462.85,1324.6 462.85,1305.12 U12.6@464.55,1303.42 ; R70.1@663.06,3714.88 663.06,3658.95 709.9,3612.12 976.77,3612.12 ; LED_PA2.1@975.21,3671.35 975.21,3613.67 976.77,3612.12 ; R38.2@1122.21,3676.35 1122.05,3676.18 1122.05,3612.12 ; K3.1@1676.02,3612.12 1453.77,3612.12 1178.02,3612.12 1122.05,3612.12 ; 976.77,3612.12 1122.05,3612.12
  Top Layer w20: R15.2@230.26,906.89 338.09,906.89 ; JP3.1@510.06,1631.88 595.11,1716.93 1070.08,1716.93 1118.95,1668.05 CN7.1@1118.95,1645.12
  Bottom Layer w15: v1(95.02,1300.12) 98.8,1300.12 103.68,1304.99 C15.2@168.88,1304.99 ; C15.2@170.02,1303.86 C15.2@168.88,1304.99 ; v1@214.89,1304.99 C15.2@168.88,1304.99 ; v1(215.02,1305.12) v2(323.79,1305.12) 383.02,1305.12 391.02,1313.12 R23.2@391.02,1353.16 ; v2(434.29,1353.16) R23.2@391.02,1353.16 ; JP3.1@510.06,1631.88 612.32,1734.14 612.32,1804.56 ; CN1.1@1115.02,1380.12 1030.02,1465.12 353.02,1465.12 340.02,1452.12 340.02,1400.87 380.77,1360.12 R23.2@391.02,1360.12 R23.2@391.02,1353.16 ; v1(1276.58,1305.84) 1377.27,1305.84 v2@1377.27,1303.37 ; v2@1377.66,1305.2 v2(1377.9,1305.2) 1404.73,1332.04 1519.42,1332.04 1598.09,1332.04 v1(1600.02,1330.12) ; JP2.1@1475.02,1647.13 JP2.1@1498.86,1647.13
  Bottom Layer w20: CN1.1@1118.95,1384.05 CN7.1@1118.95,1645.12 1169.51,1594.56 1419.46,1594.56 JP2.1@1472.03,1647.13 ; CN1.1@1122.06,1388.38 1143.48,1370.12 1386.92,1370.12 1404.73,1352.3 1404.73,1332.04 ; v2(1453.77,3610.87) 1453.77,3445.67 ; JP2.1@1475.02,1650.12 1453.77,1671.36 1453.77,3445.67 ; CN3.1@1699.61,3444.88 CN3.2@1599.61,3444.88 1454.56,3444.88 1453.77,3445.67
TVDD*: JP1.2 R34.1 | length 129
  Top Layer w20: JP1.2@335.02,1030.12 339.75,1030.12 402.1,967.76 402.1,931.63
TVDD_DISCHARGE_EN: R19.2 U15.25 | length 404.9
  Top Layer w6: R19.2@401.54,784.9 448.53,784.9 467.49,803.86 467.49,860.67 534.6,927.77 603.63,927.77 643.01,888.39 U15.25@697.7,888.39
USB_DM: R11.2 U15.32 | length 536.9
  Top Layer w6: R11.2@250.02,535.12 306.41,591.51 458.3,591.51 617.37,750.59 U15.32@697.7,750.59
USB_DP: R12.2 U15.33 | length 471.3
  Top Layer w6: R12.2@307.52,535.12 344.47,572.07 471.74,572.07 630.58,730.91 U15.33@697.7,730.91
VBAT: C30.1 CN5.22 L2.2 U18.54 | length 916
  Top Layer w11: CN5.22@163.06,2294.88 205.78,2294.88 538.54,2627.64 U18.54@658.3,2627.64 706.59,2627.64 v3(724.7,2609.52)
  Bottom Layer w15: L2.2@535.7,2592.37 651.1,2592.37 662.65,2580.82 701.15,2580.82 725.15,2604.81 725.15,2609.08 v3(724.7,2609.52)
VBUS_PYLK: F1.1 PYLK.A4 PYLK.A9 PYLK.B4 PYLK.B9 U6.5 | length 821.6
  Top Layer w10: PYLK.A4@774.83,310.01 PYLK.B9@786.64,310.01 ; PYLK.B4@963.8,310 PYLK.A9@975.62,310
  Top Layer w20: U6.5@568.17,310.12 568.99,309.29 609.6,309.29 v1(610.22,308.67) ; PYLK.B9@781.06,327.68 v4@781.06,371.57 ; PYLK.B4@969.22,328.49 v4@969.22,362.3
  Bottom Layer w15: F1.1@503.56,425.51 F1.1@493.41,415.35 493.41,414.96 493.41,412.11 595.95,309.56 609.32,309.56 v1(610.22,308.67)
  Bottom Layer w30: F1.1@493.41,414.96 737.67,414.96 v4(780.02,372.62) ; v4@780.51,372.12 925.7,372.12 ; 925.7,373.52 v4@976.73,373.52
  other v4: 977.64,372.62
VDD: C28.1 C29.1 CN5.20 JP2.2 L1.1 L2.1 R37.2 U18.52 | length 2257.4
  Top Layer w10: C28.1@480.82,2683.9 533.81,2683.88 551.06,2683.88 567.93,2667.01 U18.52@658.3,2667.01
  Top Layer w15: CN5.20@163.06,2394.88 210.58,2394.88 432.1,2616.4 v3(432.1,2642.74) 473.27,2683.9 C28.1@480.82,2683.9 ; v3(673.97,2315) 673.97,2121.7 1030.32,1765.35 1259.78,1765.35 JP2.2@1375.02,1650.12
  Bottom Layer w15: v3(432.1,2642.74) 432.69,2643.32 L1.1@475.5,2643.32 475.5,2592.57 475.7,2592.37 475.7,2513.27 v3(673.97,2315)
  Bottom Layer w20: JP2.2@1375.02,1650.12 1393.77,1668.87 1393.77,1718.47
VREFP: C31.1 C32.1 CN5.21 L1.2 U18.53 | length 1004.5
  Top Layer w10: CN5.21@63.06,2294.88 113.29,2345.12 222.13,2345.12 423.89,2546.87 524.34,2647.33 717.52,2647.33 v3(725.79,2655.6)
  Bottom Layer w15: L1.2@538.49,2643.32 542.39,2647.22 618.82,2647.22 717.41,2647.22 v3(725.79,2655.6)
pads on no net: PYLK. PYLK.A8 PYLK.B8 U15.42 U15.45

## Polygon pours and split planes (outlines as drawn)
GND on Bottom Layer "NONET_L-01_P-001" (solid, remove dead copper, pour order 3): 5.02,3865.12 1770.02,3865.12 1770.02,0.12 -3.48,0.12
GND on Top Layer "NONET_L-01_P-001" (solid, remove dead copper, pour order 4): 5.02,3865.12 1770.02,3865.12 1770.02,0.12 -3.48,0.12

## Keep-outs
Keep-Out Layer:
  lines w6: 0.02,78.86 0.02,1470.12 ; 0.02,1615.12 0.02,3779.64 ; 42.52,1515.12 142.52,1515.12 ; 42.52,1570.12 142.52,1570.12 ; 78.76,0.12 1692.93,0.12 ; 78.76,3866.18 1692.93,3866.18 ; 215.02,1515.12 565.02,1515.12 585.02,1515.12 ; 215.02,1570.12 565.02,1570.12 585.02,1570.12 ; 1260.02,1515.12 1280.02,1515.12 1560.02,1515.12 ; 1260.02,1570.12 1280.02,1570.12 1560.02,1570.12 ; 1630.02,1515.12 1730.02,1515.12 ; 1630.02,1570.12 1730.02,1570.12 ; 1771.67,78.86 1771.67,1473.46 ; 1771.67,1611.77 1771.67,3779.64
  lines w8: 0.02,78.86 ccw(c78.76,78.86) 78.76,0.12 ; 0.02,1470.12 cw(c43.77,1471.37) 42.52,1515.12 ; 0.02,1615.12 ccw(c43.77,1613.87) 42.52,1570.12 ; 0.02,3779.64 cw(c82.65,3783.54) 78.76,3866.18 ; 142.52,1515.12 ccw(c115.02,1542.62) 142.52,1570.12 ; 215.02,1515.12 cw(c242.52,1542.62) 215.02,1570.12 ; 585.02,1515.12 ccw(c557.52,1542.62) 585.02,1570.12 ; 1260.02,1515.12 cw(c1287.52,1542.62) 1260.02,1570.12 ; 1560.02,1515.12 ccw(c1532.52,1542.62) 1560.02,1570.12 ; 1630.02,1515.12 cw(c1657.52,1542.62) 1630.02,1570.12 ; 1692.93,0.12 ccw(c1692.93,78.86) 1771.67,78.86 ; 1692.93,3866.18 cw(c1689.03,3783.54) 1771.67,3779.64 ; 1730.02,1515.12 cw(c1730.02,1473.46) 1771.67,1473.46 ; 1730.02,1570.12 ccw(c1730.02,1611.77) 1771.67,1611.77

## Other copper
Top Layer:
  pour cut-out: 1655.02,1370.12 1665.02,1370.12 1665.02,1360.12 1655.02,1360.12
  pour cut-out: 275.02,490.12 285.02,490.12 285.02,480.12 275.02,480.12
  pour cut-out: 275.02,525.12 285.02,525.12 285.02,515.12 275.02,515.12
  pour cut-out: 330.02,525.12 335.52,525.12 335.52,503.12 330.02,503.12
  pour cut-out: 330.02,490.12 340.02,490.12 340.02,480.12 330.02,480.12
  region net 5V_USB_CHGR: 385.02,235.12 395.02,245.12 420.02,245.12 465.02,200.12 510.02,200.12 530.02,180.12 660.02,180.12 660.02,120.12 515.02,120.12 515.02,140.12 490.02,165.12 435.02,165.12 400.02,200.11 385.02,215.11
  region net 3V3_PYLK: 240.02,315.12 290.02,315.12 310.02,295.12 355.02,295.12 360.02,290.12 360.02,250.12 345.02,235.12 345.02,165.12 362.52,147.62 355.02,140.12 293.41,140.12 293.41,153.6 305.02,165.21 305.02,230.12 280.02,255.12 240.02,255.12
  region net 3V3_PYLK: 1095.02,155.12 1105.02,165.12 1125.02,165.12 1135.02,155.12 1135.02,130.12 1140.02,125.12 1185.02,125.12 1190.02,120.12 1190.02,105.12 1185.02,100.12 1130.02,100.12 1095.02,135.12
  region net 3V3_USB_PYLK: 1227.52,120.12 1300.02,120.12 1315.02,135.12 1335.02,135.12 1345.02,125.12 1345.02,105.12 1330.02,90.12 1315.02,90.12 1290.02,65.12 1290.02,25.12 1225.02,25.12 1225.02,118.45
  pour cut-out: 390.02,495.12 400.02,495.12 400.02,485.12 390.02,485.12
  pour cut-out: 445.02,495.12 455.02,495.12 455.02,485.12 445.02,485.12
  pour cut-out: 1627.45,1037.11 1637.45,1037.11 1637.45,1027.11 1627.45,1027.11
  pour cut-out: 1675.02,1075.12 1685.02,1075.12 1685.02,1065.12 1675.02,1065.12

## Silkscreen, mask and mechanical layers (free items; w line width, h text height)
Top Overlay:
  drawing of 1057 lines, arcs and shapes, not listed
  text "NRST" at 199.06,3519.66 h55
  text "USER_PA0" at 1412.06,3519.65 h55
  text "GND" at 227.17,3431.71 h55
  text "GND" at 353.54,3431.71 h55
  text "VDD*" at 1302.41,3424.02 h55
  text "VDD*" at 1438.63,3424.02 h55
  text "32" at 1576.06,3364.44 h50
  text "31" at 1677.06,3364.44 h50
  text "33" at 42.06,3360.44 h50
  text "34" at 145.06,3360.44 h50
  text "D6" at 1318.02,3283.49 h55
  text "D5" at 1471.26,3283.49 h55
  text "D7" at 227.06,3281.88 h55
  text "D8" at 361.76,3282.49 h55
  text "D4" at 1318.02,3183.78 h55
  text "D3" at 1471.57,3183.01 h55
  text "D9" at 227.06,3181.86 h55
  text "D10" at 338.06,3181.49 h55
  text "D2" at 1318.02,3083.97 h55
  text "D1" at 1478.96,3082.88 h55
  text "D11" at 227.06,3081.9 h55
  text "D12" at 343.06,3080.88 h55
  text "D0" at 1318.02,2983.61 h55
  text "A0" at 227.06,2981.88 h55
  text "A1" at 368.05,2982.28 h55
  text "C15" at 1440.02,2982.3 h55
  text "C14" at 1318.02,2882.73 h55
  text "A2" at 227.06,2881.92 h55
  text "A3" at 360.65,2882.09 h55
  text "C13" at 1440.32,2881.47 h55
  text "A4" at 227.06,2782.24 h55
  text "A5" at 360.35,2781.93 h55
  text "C12" at 1318.02,2781.85 h55
  text "C11" at 1447.72,2780.74 h55
  text "A6" at 360.65,2683.49 h55
  text "D13" at 227.06,2682.15 h55
  text "C10" at 1318.02,2680.98 h55
  text "C9" at 1470.01,2679.98 h55
  text "A7" at 227.06,2582.31 h55
  text "A8" at 360.57,2581.34 h55
  text "C8" at 1318.02,2580.1 h55
  text "C7" at 1470.1,2579.22 h55
  text "A9" at 227.06,2482.3 h55
  text "A10" at 345.06,2481.49 h55
  text "C6" at 1318.02,2479.22 h55
  text "C5" at 1469.79,2478.46 h55
  text "GND" at 227.06,2381.74 h55
  text "VDD" at 359.11,2381.88 h55
  text "C4" at 1318.02,2378.35 h55
  text "C3" at 1470.1,2377.63 h55
  text "C2" at 1318.02,2277.47 h55
  text "C1" at 1477.49,2276.9 h55
  text "VBAT" at 365.09,2236.92 h55 r45
  text "VREFP" at 245.09,2225.92 h55 r45
  text "A14" at 348.06,2185.88 h55
  text "A13" at 227.06,2181.78 h55
  text "C0" at 1318.02,2176.6 h55
  text "B15" at 1444.25,2176.49 h55
  text "PY32T092-START V2.1" at 636.02,2098.32 h65
  text "A15" at 227.06,2081.62 h55
  text "B0" at 364.75,2081.34 h55
  text "B14" at 1318.02,2076.76 h55
  text "B13" at 1444.56,2076.01 h55
  text "2025-12" at 840,1997.36 h65
  text "B1" at 227.06,1981.66 h55
  text "B2" at 365,1981.28 h55
  text "B12" at 1318.02,1976.95 h55
  text "B11" at 1451.95,1975.88 h55
  text "B3" at 227.06,1881.57 h55
  text "B4" at 364.75,1881.51 h55
  text "B10" at 1318.02,1876.58 h55
  text "B9" at 1474.25,1875.66 h55
  text "B5" at 227.06,1781.49 h55
  text "B6" at 364.62,1781.4 h55
  text "B8" at 1318.02,1776.19 h55
  text "B7" at 1474.34,1775.58 h55
  text "NRST" at 735.45,1712.88 h55 r90
  text "SWC" at 836.25,1712.88 h55 r90
  text "GND" at 937.04,1712.88 h55 r90
  text "SWD" at 1037.84,1712.88 h55 r90
  text "VDD*" at 1138.06,1712.93 h55 r90
  text "VDD" at 1326.25,1700.11 h40
  text "VDD*" at 1436.95,1700.11 h40
  text "2" at 1588.01,1695.88 h50
  text "1" at 1690.06,1695.88 h50
  text "63" at 43.06,1694.39 h50
  text "64" at 141.06,1694.44 h50
  text "VDD*" at 500.1,1682.88 h40
  text "GND" at 259.02,1682.56 h40
  text "BOOT0" at 359.02,1682.56 h40
  text "IDD" at 1527.12,1632.32 h40
  text "BOOT_SEL" at 75.06,1618.99 h40
  text "NRST" at 632.06,1451.44 h50
  text "SWC" at 764.06,1451.44 h50
  text "GND" at 882.06,1451.44 h50
  text "SWD" at 987.06,1451.44 h50
  text "VDD*" at 1098.11,1451.44 h50
  text "SWO" at 652.06,1176.55 h50
  text "RTS" at 775.06,1176.55 h50
  text "DTR" at 882.06,1176 h50
  text "TX" at 996.32,1176 h50
  text "RX" at 1090.02,1176 h50
  text "5V" at 198.06,1078.44 h50
  text "VDD*" at 284.11,1077.88 h50
  text "3V3" at 413.06,1076.44 h50
  text "BT0" at 1135.5,413.88 h50 r90
  text "VDD" at 1233.96,413.93 h50 r90
  text "DIO" at 1333.46,413.88 h50 r90
  text "GND" at 1432.98,413.88 h50 r90
  text "CLK" at 1532.5,413.88 h50 r90
  text "PY-LINK OB V2.1" at 614.96,398.89 h65
Bottom Overlay:
Mechanical 1:
  lines w6: 215.02,1515.12 565.02,1515.12 585.02,1515.12 ; 215.02,1570.12 565.02,1570.12 585.02,1570.12 ; 1260.02,1515.12 1280.02,1515.12 1560.02,1515.12 ; 1260.02,1570.12 1280.02,1570.12 1560.02,1570.12
  lines w8: 215.02,1515.12 cw(c242.52,1542.62) 215.02,1570.12 ; 585.02,1515.12 ccw(c557.52,1542.62) 585.02,1570.12 ; 1260.02,1515.12 cw(c1287.52,1542.62) 1260.02,1570.12 ; 1560.02,1515.12 ccw(c1532.52,1542.62) 1560.02,1570.12

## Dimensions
42.52,1570.12 to 78.76,3866.18 on Mechanical 1
1771.67,78.86 to 1819.7,3863.11 on Mechanical 1
78.76,0.12 to -4.98,1505.12 on Mechanical 1
0.02,78.86 to 1771.67,78.86 on Mechanical 1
